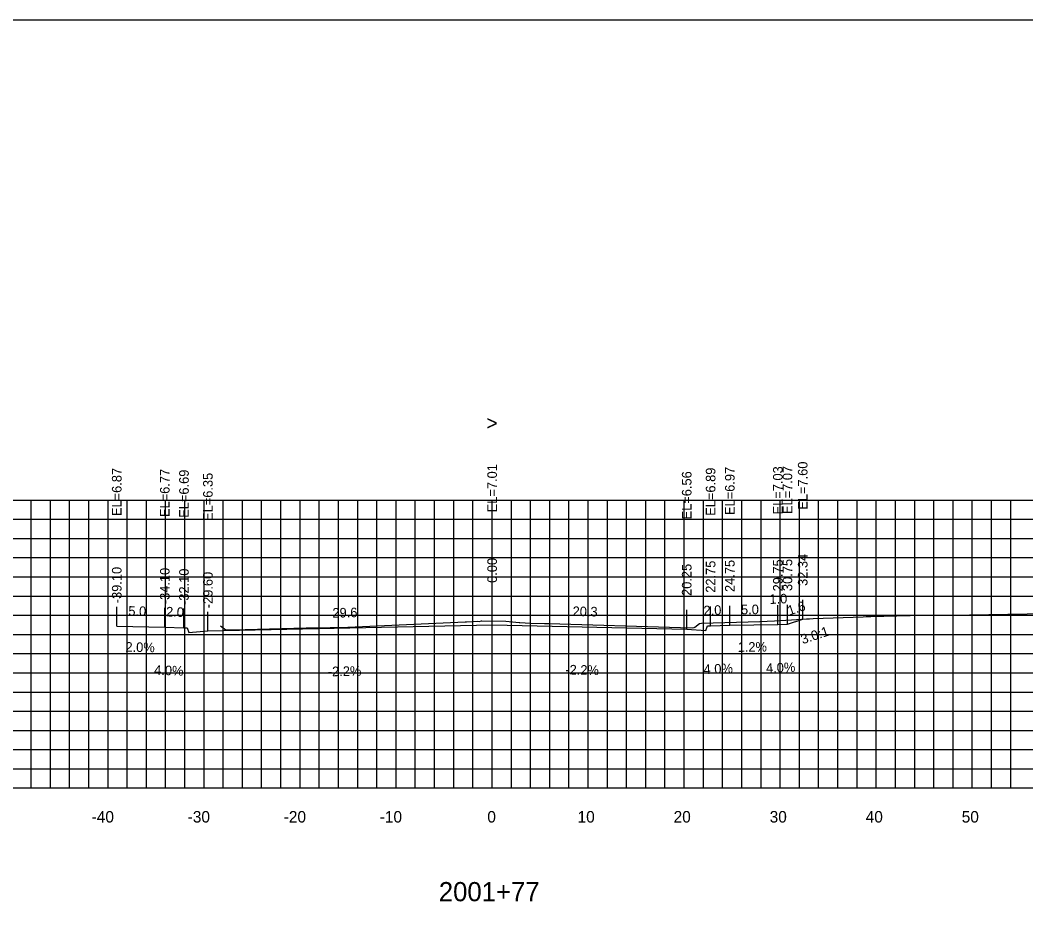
# Model space of a CAD drawing. Extents: x 1800876 to 1802446, y 250079 to 250269.
# Drawn here: x 1802241.8 to 1802346.6, y 250174.9 to 250269.4 of the extents above; entities that cross this region are included whole.
import ezdxf

# ---------------------------------------------------------------- set-up
doc = ezdxf.new("R2010")
doc.units = 0
for name, color, linetype in [('1', 7, 'Continuous'), ('10', 7, 'Continuous'), ('3', 7, 'Continuous'), ('4', 7, 'Continuous'), ('60', 7, 'Continuous'), ('CL-CNST', 7, 'Continuous'), ('Level 62', 7, 'Continuous'), ('M-ROADS', 7, 'Continuous')]:
    doc.layers.add(name, color=color, linetype=linetype)

msp = doc.modelspace()

# ---------------------------------------------------------------- linework, layer by layer
for p, q in [((1802251.91, 250206.3), (1802251.91, 250208.3)), ((1802256.91, 250206.2), (1802256.91, 250208.2)), ((1802258.91, 250206.12), (1802258.91, 250208.12)), ((1802291, 250206.44), (1802291, 250208.44)), ((1802313.75, 250206.33), (1802313.75, 250208.33)), ((1802315.75, 250206.41), (1802315.75, 250208.41)), ((1802320.75, 250206.47), (1802320.75, 250208.47)), ((1802321.75, 250206.51), (1802321.75, 250208.51)), ((1802323.34, 250207.03), (1802323.34, 250209.03)), ((1802261.4, 250205.79), (1802261.4, 250207.79)), ((1802311.26, 250205.99), (1802311.26, 250207.99))]:
    msp.add_line(p, q)
msp.add_lwpolyline([(1802141, 250079.43), (1802441, 250079.43), (1802441, 250269.43), (1802141, 250269.43)], close=True)
at = {"layer": '60'}
for p, q in [((1802141, 250189.43), (1802441, 250189.43)), ((1802251, 250189.37), (1802251, 250189.43)), ((1802261, 250189.37), (1802261, 250189.43)), ((1802271, 250189.37), (1802271, 250189.43)), ((1802281, 250189.37), (1802281, 250189.43)), ((1802291, 250189.37), (1802291, 250189.43)), ((1802301, 250189.37), (1802301, 250189.43)), ((1802311, 250189.37), (1802311, 250189.43)), ((1802321, 250189.37), (1802321, 250189.43)), ((1802331, 250189.37), (1802331, 250189.43)), ((1802341, 250189.37), (1802341, 250189.43))]:
    msp.add_line(p, q, dxfattribs=at)
at = {"layer": 'CL-CNST'}
msp.add_lwpolyline([(1802251.91, 250206.3), (1802256.91, 250206.2), (1802258.91, 250206.12), (1802259.24, 250206.12), (1802259.4, 250205.62), (1802261.4, 250205.79), (1802291, 250206.44), (1802311.26, 250205.99), (1802313.26, 250205.83), (1802313.42, 250206.33), (1802313.75, 250206.33), (1802315.75, 250206.41), (1802320.75, 250206.47), (1802321.75, 250206.51), (1802323.34, 250207.03)], dxfattribs=at)
at = {"layer": 'Level 62'}
for p, q in [((1802141, 250219.43), (1802441, 250219.43)), ((1802243, 250189.43), (1802243, 250219.43)), ((1802245, 250189.43), (1802245, 250219.43)), ((1802247, 250189.43), (1802247, 250219.43)), ((1802249, 250189.43), (1802249, 250219.43)), ((1802251, 250189.43), (1802251, 250219.43)), ((1802253, 250189.43), (1802253, 250219.43)), ((1802255, 250189.43), (1802255, 250219.43)), ((1802257, 250189.43), (1802257, 250219.43)), ((1802259, 250189.43), (1802259, 250219.43)), ((1802261, 250189.43), (1802261, 250219.43)), ((1802263, 250189.43), (1802263, 250219.43)), ((1802265, 250189.43), (1802265, 250219.43)), ((1802267, 250189.43), (1802267, 250219.43)), ((1802269, 250189.43), (1802269, 250219.43)), ((1802271, 250189.43), (1802271, 250219.43)), ((1802273, 250189.43), (1802273, 250219.43)), ((1802275, 250189.43), (1802275, 250219.43)), ((1802277, 250189.43), (1802277, 250219.43)), ((1802279, 250189.43), (1802279, 250219.43)), ((1802281, 250189.43), (1802281, 250219.43)), ((1802283, 250189.43), (1802283, 250219.43)), ((1802285, 250189.43), (1802285, 250219.43)), ((1802287, 250189.43), (1802287, 250219.43)), ((1802289, 250189.43), (1802289, 250219.43)), ((1802291, 250189.43), (1802291, 250219.43)), ((1802293, 250189.43), (1802293, 250219.43)), ((1802295, 250189.43), (1802295, 250219.43)), ((1802297, 250189.43), (1802297, 250219.43)), ((1802299, 250189.43), (1802299, 250219.43)), ((1802301, 250189.43), (1802301, 250219.43)), ((1802303, 250189.43), (1802303, 250219.43)), ((1802305, 250189.43), (1802305, 250219.43)), ((1802307, 250189.43), (1802307, 250219.43)), ((1802309, 250189.43), (1802309, 250219.43)), ((1802311, 250189.43), (1802311, 250219.43)), ((1802313, 250189.43), (1802313, 250219.43)), ((1802315, 250189.43), (1802315, 250219.43)), ((1802317, 250189.43), (1802317, 250219.43)), ((1802319, 250189.43), (1802319, 250219.43)), ((1802321, 250189.43), (1802321, 250219.43)), ((1802323, 250189.43), (1802323, 250219.43)), ((1802325, 250189.43), (1802325, 250219.43)), ((1802327, 250189.43), (1802327, 250219.43)), ((1802329, 250189.43), (1802329, 250219.43)), ((1802331, 250189.43), (1802331, 250219.43)), ((1802333, 250189.43), (1802333, 250219.43)), ((1802335, 250189.43), (1802335, 250219.43)), ((1802337, 250189.43), (1802337, 250219.43)), ((1802339, 250189.43), (1802339, 250219.43)), ((1802341, 250189.43), (1802341, 250219.43)), ((1802343, 250189.43), (1802343, 250219.43)), ((1802345, 250189.43), (1802345, 250219.43)), ((1802141, 250217.43), (1802441, 250217.43)), ((1802141, 250215.43), (1802441, 250215.43)), ((1802141, 250213.43), (1802441, 250213.43)), ((1802141, 250211.43), (1802441, 250211.43)), ((1802141, 250209.43), (1802441, 250209.43)), ((1802141, 250207.43), (1802441, 250207.43)), ((1802141, 250205.43), (1802441, 250205.43)), ((1802141, 250203.43), (1802441, 250203.43)), ((1802141, 250201.43), (1802441, 250201.43)), ((1802141, 250199.43), (1802441, 250199.43)), ((1802141, 250197.43), (1802441, 250197.43)), ((1802141, 250195.43), (1802441, 250195.43)), ((1802141, 250193.43), (1802441, 250193.43)), ((1802141, 250191.43), (1802441, 250191.43)), ((1802141, 250189.43), (1802441, 250189.43))]:
    msp.add_line(p, q, dxfattribs=at)
at = {"layer": 'M-ROADS'}
msp.add_lwpolyline([(1802262.71, 250206.32), (1802263.28, 250205.9), (1802265.27, 250205.95), (1802271.65, 250206.1), (1802274.14, 250206.15), (1802274.58, 250206.16), (1802274.58, 250206.16), (1802274.63, 250206.16), (1802274.66, 250206.16), (1802274.68, 250206.16), (1802274.84, 250206.16), (1802275.33, 250206.16), (1802275.98, 250206.2), (1802288.2, 250206.75), (1802288.33, 250206.75), (1802289.46, 250206.8), (1802289.66, 250206.79), (1802289.89, 250206.85), (1802289.89, 250206.85), (1802289.94, 250206.85), (1802292.44, 250206.81), (1802293.82, 250206.66), (1802293.89, 250206.66), (1802294.43, 250206.64), (1802295, 250206.62), (1802296.46, 250206.58), (1802296.92, 250206.57), (1802310.62, 250206.14), (1802311.86, 250206.1), (1802312.01, 250206.14), (1802312.05, 250206.14), (1802312.11, 250206.19), (1802312.61, 250206.58), (1802312.79, 250206.61), (1802318.88, 250206.79), (1802320.41, 250206.84), (1802322.19, 250206.96), (1802323.72, 250207.06), (1802324.05, 250207.06), (1802324.44, 250207.08), (1802329.62, 250207.27), (1802329.95, 250207.28), (1802330.45, 250207.3), (1802335.9, 250207.43), (1802336.02, 250207.43), (1802336.4, 250207.43), (1802338.69, 250207.45), (1802348.71, 250207.61)], dxfattribs=at)

# ---------------------------------------------------------------- texts
msp.add_text('3.0:1', height=1, rotation=18.4349).set_placement((1802323.34, 250204.4))
at = {"layer": '1'}
msp.add_text('2001+77', height=2, dxfattribs=at).set_placement((1802285.45, 250177.63))
at = {"layer": '10'}
for s, p in [('-40', (1802249.3, 250185.83)), ('-30', (1802259.3, 250185.83)), ('-20', (1802269.3, 250185.83)), ('-10', (1802279.3, 250185.83)), ('0', (1802290.5, 250185.83)), ('10', (1802299.9, 250185.83)), ('20', (1802309.9, 250185.83)), ('30', (1802319.9, 250185.83)), ('40', (1802329.9, 250185.83)), ('50', (1802339.9, 250185.83))]:
    msp.add_text(s, height=1.2, dxfattribs=at).set_placement(p)
at = {"layer": '3'}
for s, p in [('EL=7.01', (1802291.5, 250218.15)), ('EL=6.97', (1802316.25, 250217.87)), ('EL=7.03', (1802321.25, 250217.93)), ('EL=7.07', (1802322.25, 250217.97)), ('EL=7.60', (1802323.84, 250218.42)), ('EL=6.87', (1802252.41, 250217.76)), ('EL=6.77', (1802257.41, 250217.66)), ('EL=6.69', (1802259.41, 250217.58)), ('EL=6.35', (1802261.9, 250217.25)), ('EL=6.56', (1802311.76, 250217.41)), ('EL=6.89', (1802314.25, 250217.79)), ('0.00', (1802291.5, 250210.8)), ('32.34', (1802323.84, 250210.48)), ('-39.10', (1802252.41, 250208.68)), ('-34.10', (1802257.41, 250208.58)), ('20.25', (1802311.76, 250209.44)), ('22.75', (1802314.25, 250209.77)), ('24.75', (1802316.25, 250209.85)), ('29.75', (1802321.25, 250209.91)), ('30.75', (1802322.25, 250209.95)), ('-32.10', (1802259.41, 250208.5)), ('-29.60', (1802261.9, 250208.16))]:
    msp.add_text(s, height=1, rotation=90, dxfattribs=at).set_placement(p)
at = {"layer": '4'}
for s, rotation, p in [('1.0', 2.2906, (1802319.89, 250208.6)), ('5.0', 358.8542, (1802253.11, 250207.38)), ('2.0', 357.7094, (1802257.03, 250207.31)), ('29.6', 1.2603, (1802274.38, 250207.17)), ('20.3', 358.7397, (1802299.37, 250207.35)), ('2.0', 2.2906, (1802313.03, 250207.41)), ('5.0', 0.6875, (1802316.92, 250207.52)), ('1.6', 18.4349, (1802321.96, 250207.4)), ('2.0%', 358.8542, (1802252.81, 250203.63)), ('1.2%', 0.6875, (1802316.57, 250203.61)), ('4.0%', 357.7094, (1802255.79, 250201.24)), ('-2.2%', 1.2603, (1802273.9, 250201.06)), ('-2.2%', 358.7397, (1802298.61, 250201.27)), ('4.0%', 2.2906, (1802313.04, 250201.29)), ('4.0%', 2.2906, (1802319.54, 250201.41))]:
    msp.add_text(s, height=1, rotation=rotation, dxfattribs=at).set_placement(p)
at = {"layer": '60'}
msp.add_text('>', height=1.5, dxfattribs=at).set_placement((1802290.39, 250226.71))

doc.saveas('drawing.dxf')
